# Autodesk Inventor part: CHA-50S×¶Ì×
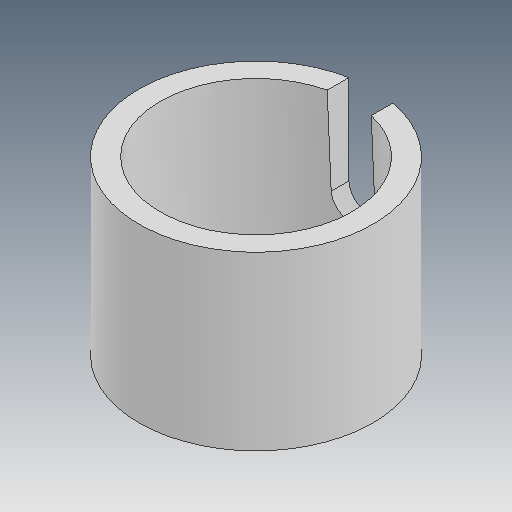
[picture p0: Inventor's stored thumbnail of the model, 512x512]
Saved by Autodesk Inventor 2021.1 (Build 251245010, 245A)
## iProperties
Created: 2019-12
Part Number: CHA-50S×¶Ì×
Material: Ogólny
Document SubType Name: Modeling
Designer: user
Density: 1 g/cm^3
Appearance: Domyślna
Author: user
Revision Number: ÈÎºÎ
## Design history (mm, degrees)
feature "ÊäÈë1"
node "Bryła1"
